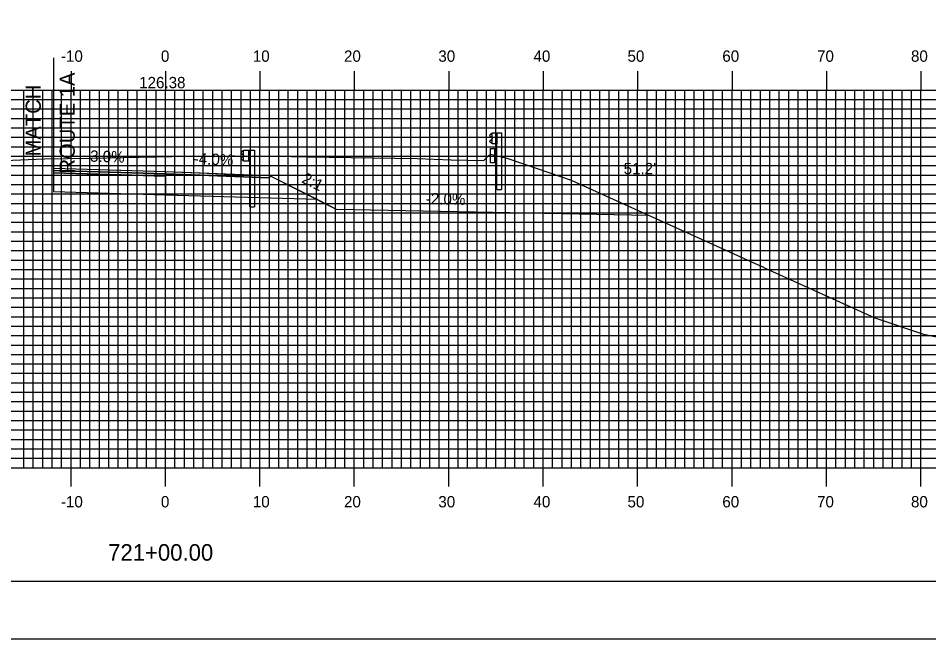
# Model space of a CAD drawing. Extents: x 858445 to 858788, y 364366 to 364586.
# Drawn here: x 858595.3 to 858691.7, y 364365.7 to 364431.4 of the extents above; entities that cross this region are included whole.
import ezdxf

# ---------------------------------------------------------------- set-up
doc = ezdxf.new("R2010")
doc.units = 0
for name, color, linetype in [('ANNOTATION', 7, 'Continuous'), ('BORDER', 7, 'Continuous'), ('D_Guardrail_Beam_Lt', 7, 'Continuous'), ('D_Roadway_Centerline', 7, 'Continuous'), ('D_Roadway_Centerline_Text', 7, 'Continuous'), ('D_Roadway_Edge_Shoulder', 7, 'Continuous'), ('D_Roadway_Edge_TW', 7, 'Continuous'), ('D_Roadway_Pavement', 7, 'Continuous'), ('D_Roadway_SlopeLines', 7, 'Continuous'), ('D_Roadway_SubGrade', 7, 'Continuous'), ('D_Text_Standard', 7, 'Continuous'), ('H_V ANNOTATION', 7, 'Continuous'), ('M_Roadway_Centerline', 7, 'Continuous'), ('MAJOR', 7, 'Continuous'), ('MINOR', 7, 'Continuous'), ('PLOT BOUNDARY', 7, 'Continuous'), ('S_Curb_Type_1', 7, 'Continuous'), ('S_Guardrail_Beam', 7, 'Continuous'), ('S_Roadway_Centerline', 7, 'Continuous')]:
    doc.layers.add(name, color=color, linetype=linetype)

msp = doc.modelspace()

# ---------------------------------------------------------------- linework, layer by layer
at = {"layer": 'BORDER'}
msp.add_lwpolyline([(858461.275, 364371.787), (858781.275, 364371.787), (858781.275, 364581.787), (858461.275, 364581.787)], close=True, dxfattribs=at)
at = {"layer": 'D_Guardrail_Beam_Lt'}
for p, q in [((858619.056, 364417.325), (858618.912, 364417.225)), ((858618.912, 364417.082), (858619.107, 364416.946)), ((858619.146, 364417.347), (858619.071, 364417.332)), ((858619.146, 364417.43), (858619.833, 364417.43)), ((858619.146, 364416.263), (858619.146, 364417.43)), ((858619.666, 364417.43), (858619.666, 364416.263)), ((858619.771, 364417.43), (858619.771, 364416.263)), ((858619.833, 364417.43), (858620.304, 364417.43)), ((858619.833, 364417.43), (858619.833, 364416.263)), ((858620.304, 364417.43), (858620.304, 364411.43)), ((858619.107, 364416.747), (858618.912, 364416.611)), ((858618.912, 364416.468), (858619.056, 364416.368)), ((858619.071, 364416.361), (858619.146, 364416.347)), ((858619.141, 364416.882), (858619.141, 364416.812)), ((858619.833, 364416.263), (858619.146, 364416.263)), ((858619.812, 364411.43), (858619.812, 364416.263)), ((858619.812, 364411.43), (858620.304, 364411.43))]:
    msp.add_line(p, q, dxfattribs=at)
for centre, major_axis, start_param, end_param in [((858618.962, 364417.154), (-0.0877, 0), 5.323254, 7.243116), ((858619.079, 364417.291), (-0.0417, 0), 4.907132, 5.323254), ((858618.962, 364416.54), (-0.0877, 0), 5.323254, 7.243116), ((858619.079, 364416.402), (-0.0417, 0), 0.959931, 1.376053), ((858619.062, 364416.882), (0.0789, 0), 0, 0.959931), ((858619.062, 364416.812), (0.0789, 0), 5.323254, 6.283185)]:
    msp.add_ellipse(centre, major_axis=major_axis, ratio=0.995501, start_param=start_param, end_param=end_param, dxfattribs=at)
at = {"layer": 'D_Roadway_Centerline'}
msp.add_lwpolyline([(858599.008, 364415.522), (858603.741, 364415.381), (858610.875, 364415.167), (858615.281, 364414.99), (858618.875, 364414.847), (858620.526, 364414.781), (858621.875, 364414.727), (858624.674, 364413.327), (858626.96, 364412.184), (858628.06, 364411.634), (858628.96, 364411.184), (858647.257, 364410.818), (858662.073, 364410.522)], dxfattribs=at)
at = {"layer": 'D_Roadway_Edge_Shoulder'}
for points in [[(858610.875, 364415.167), (858621.875, 364414.727), (858621.875, 364414.477), (858610.875, 364414.917)], [(858610.875, 364415.167), (858618.875, 364414.847), (858618.875, 364414.847), (858621.875, 364414.727), (858621.875, 364414.477), (858610.875, 364414.917)]]:
    msp.add_lwpolyline(points, close=True, dxfattribs=at)
at = {"layer": 'D_Roadway_Edge_TW'}
msp.add_lwpolyline([(858599.008, 364415.522), (858610.875, 364415.167), (858610.875, 364414.917), (858599.008, 364415.272)], dxfattribs=at)
msp.add_lwpolyline([(858599.008, 364415.522), (858610.875, 364415.167), (858610.875, 364414.917), (858599.008, 364415.272)], dxfattribs=at)
msp.add_lwpolyline([(858599.008, 364415.522), (858610.875, 364415.167), (858610.875, 364414.917), (858599.008, 364415.272)], dxfattribs=at)
at = {"layer": 'D_Roadway_Pavement'}
for points in [[(858599.008, 364415.272), (858610.875, 364414.917), (858610.875, 364414.667), (858599.008, 364415.022)], [(858599.008, 364415.272), (858610.875, 364414.917), (858610.875, 364414.667), (858599.008, 364415.022)], [(858599.008, 364415.272), (858610.875, 364414.917), (858610.875, 364414.667), (858599.008, 364415.022)], [(858610.875, 364414.917), (858610.875, 364414.667)], [(858610.875, 364414.917), (858610.875, 364414.667)], [(858610.875, 364414.917), (858610.875, 364414.667)], [(858610.875, 364414.917), (858610.875, 364414.667)]]:
    msp.add_lwpolyline(points, dxfattribs=at)
at = {"layer": 'D_Roadway_SlopeLines'}
for points in [[(858621.875, 364414.727), (858628.96, 364411.184)], [(858628.96, 364411.184), (858662.073, 364410.522)]]:
    msp.add_lwpolyline(points, dxfattribs=at)
at = {"layer": 'D_Roadway_SubGrade'}
msp.add_line((858599.008, 364427.215), (858599.008, 364413.022), dxfattribs=at)
msp.add_lwpolyline([(858599.008, 364415.022), (858610.875, 364414.667), (858610.875, 364412.667), (858599.008, 364413.022)], dxfattribs=at)
msp.add_lwpolyline([(858599.008, 364415.022), (858610.875, 364414.667), (858610.875, 364412.667), (858599.008, 364413.022)], dxfattribs=at)
msp.add_lwpolyline([(858599.008, 364415.022), (858610.875, 364414.667), (858610.875, 364412.667), (858599.008, 364413.022)], dxfattribs=at)
msp.add_lwpolyline([(858610.875, 364414.667), (858610.875, 364414.917), (858621.875, 364414.477), (858621.875, 364414.727), (858626.96, 364412.184), (858610.875, 364412.667)], close=True, dxfattribs=at)
at = {"layer": 'MAJOR'}
for p, q in [((858600.875, 364425.791), (858600.875, 364423.787)), ((858610.875, 364425.791), (858610.875, 364423.787)), ((858620.875, 364425.791), (858620.875, 364423.787)), ((858630.875, 364425.791), (858630.875, 364423.787)), ((858640.875, 364425.791), (858640.875, 364423.787)), ((858650.875, 364425.791), (858650.875, 364423.787)), ((858660.875, 364425.791), (858660.875, 364423.787)), ((858670.875, 364425.791), (858670.875, 364423.787)), ((858680.875, 364425.791), (858680.875, 364423.787)), ((858690.875, 364425.791), (858690.875, 364423.787)), ((858470.875, 364423.787), (858750.875, 364423.787)), ((858470.875, 364423.787), (858750.875, 364423.787)), ((858600.875, 364383.787), (858600.875, 364423.787)), ((858610.875, 364383.787), (858610.875, 364423.787)), ((858620.875, 364383.787), (858620.875, 364423.787)), ((858630.875, 364383.787), (858630.875, 364423.787)), ((858640.875, 364383.787), (858640.875, 364423.787)), ((858650.875, 364383.787), (858650.875, 364423.787)), ((858660.875, 364383.787), (858660.875, 364423.787)), ((858670.875, 364383.787), (858670.875, 364423.787)), ((858680.875, 364383.787), (858680.875, 364423.787)), ((858690.875, 364383.787), (858690.875, 364423.787)), ((858470.875, 364418.787), (858750.875, 364418.787)), ((858470.875, 364413.787), (858750.875, 364413.787)), ((858470.875, 364408.787), (858750.875, 364408.787)), ((858470.875, 364403.787), (858750.875, 364403.787)), ((858470.875, 364398.787), (858750.875, 364398.787)), ((858470.875, 364393.787), (858750.875, 364393.787)), ((858470.875, 364388.787), (858750.875, 364388.787)), ((858470.875, 364383.787), (858750.875, 364383.787)), ((858470.875, 364383.787), (858750.875, 364383.787)), ((858600.875, 364381.783), (858600.875, 364383.787)), ((858610.875, 364381.783), (858610.875, 364383.787)), ((858620.875, 364381.783), (858620.875, 364383.787)), ((858630.875, 364381.783), (858630.875, 364383.787)), ((858640.875, 364381.783), (858640.875, 364383.787)), ((858650.875, 364381.783), (858650.875, 364383.787)), ((858660.875, 364381.783), (858660.875, 364383.787)), ((858670.875, 364381.783), (858670.875, 364383.787)), ((858680.875, 364381.783), (858680.875, 364383.787)), ((858690.875, 364381.783), (858690.875, 364383.787))]:
    msp.add_line(p, q, dxfattribs=at)
at = {"layer": 'MINOR'}
for p, q in [((858595.875, 364383.787), (858595.875, 364423.787)), ((858596.875, 364383.787), (858596.875, 364423.787)), ((858597.875, 364383.787), (858597.875, 364423.787)), ((858598.875, 364383.787), (858598.875, 364423.787)), ((858599.875, 364383.787), (858599.875, 364423.787)), ((858601.875, 364383.787), (858601.875, 364423.787)), ((858602.875, 364383.787), (858602.875, 364423.787)), ((858603.875, 364383.787), (858603.875, 364423.787)), ((858604.875, 364383.787), (858604.875, 364423.787)), ((858605.875, 364383.787), (858605.875, 364423.787)), ((858606.875, 364383.787), (858606.875, 364423.787)), ((858607.875, 364383.787), (858607.875, 364423.787)), ((858608.875, 364383.787), (858608.875, 364423.787)), ((858609.875, 364383.787), (858609.875, 364423.787)), ((858611.875, 364383.787), (858611.875, 364423.787)), ((858612.875, 364383.787), (858612.875, 364423.787)), ((858613.875, 364383.787), (858613.875, 364423.787)), ((858614.875, 364383.787), (858614.875, 364423.787)), ((858615.875, 364383.787), (858615.875, 364423.787)), ((858616.875, 364383.787), (858616.875, 364423.787)), ((858617.875, 364383.787), (858617.875, 364423.787)), ((858618.875, 364383.787), (858618.875, 364423.787)), ((858619.875, 364383.787), (858619.875, 364423.787)), ((858621.875, 364383.787), (858621.875, 364423.787)), ((858622.875, 364383.787), (858622.875, 364423.787)), ((858623.875, 364383.787), (858623.875, 364423.787)), ((858624.875, 364383.787), (858624.875, 364423.787)), ((858625.875, 364383.787), (858625.875, 364423.787)), ((858626.875, 364383.787), (858626.875, 364423.787)), ((858627.875, 364383.787), (858627.875, 364423.787)), ((858628.875, 364383.787), (858628.875, 364423.787)), ((858629.875, 364383.787), (858629.875, 364423.787)), ((858631.875, 364383.787), (858631.875, 364423.787)), ((858632.875, 364383.787), (858632.875, 364423.787)), ((858633.875, 364383.787), (858633.875, 364423.787)), ((858634.875, 364383.787), (858634.875, 364423.787)), ((858635.875, 364383.787), (858635.875, 364423.787)), ((858636.875, 364383.787), (858636.875, 364423.787)), ((858637.875, 364383.787), (858637.875, 364423.787)), ((858638.875, 364383.787), (858638.875, 364423.787)), ((858639.875, 364383.787), (858639.875, 364423.787)), ((858641.875, 364383.787), (858641.875, 364423.787)), ((858642.875, 364383.787), (858642.875, 364423.787)), ((858643.875, 364383.787), (858643.875, 364423.787)), ((858644.875, 364383.787), (858644.875, 364423.787)), ((858645.875, 364383.787), (858645.875, 364423.787)), ((858646.875, 364383.787), (858646.875, 364423.787)), ((858647.875, 364383.787), (858647.875, 364423.787)), ((858648.875, 364383.787), (858648.875, 364423.787)), ((858649.875, 364383.787), (858649.875, 364423.787)), ((858651.875, 364383.787), (858651.875, 364423.787)), ((858652.875, 364383.787), (858652.875, 364423.787)), ((858653.875, 364383.787), (858653.875, 364423.787)), ((858654.875, 364383.787), (858654.875, 364423.787)), ((858655.875, 364383.787), (858655.875, 364423.787)), ((858656.875, 364383.787), (858656.875, 364423.787)), ((858657.875, 364383.787), (858657.875, 364423.787)), ((858658.875, 364383.787), (858658.875, 364423.787)), ((858659.875, 364383.787), (858659.875, 364423.787)), ((858661.875, 364383.787), (858661.875, 364423.787)), ((858662.875, 364383.787), (858662.875, 364423.787)), ((858663.875, 364383.787), (858663.875, 364423.787)), ((858664.875, 364383.787), (858664.875, 364423.787)), ((858665.875, 364383.787), (858665.875, 364423.787)), ((858666.875, 364383.787), (858666.875, 364423.787)), ((858667.875, 364383.787), (858667.875, 364423.787)), ((858668.875, 364383.787), (858668.875, 364423.787)), ((858669.875, 364383.787), (858669.875, 364423.787)), ((858671.875, 364383.787), (858671.875, 364423.787)), ((858672.875, 364383.787), (858672.875, 364423.787)), ((858673.875, 364383.787), (858673.875, 364423.787)), ((858674.875, 364383.787), (858674.875, 364423.787)), ((858675.875, 364383.787), (858675.875, 364423.787)), ((858676.875, 364383.787), (858676.875, 364423.787)), ((858677.875, 364383.787), (858677.875, 364423.787)), ((858678.875, 364383.787), (858678.875, 364423.787)), ((858679.875, 364383.787), (858679.875, 364423.787)), ((858681.875, 364383.787), (858681.875, 364423.787)), ((858682.875, 364383.787), (858682.875, 364423.787)), ((858683.875, 364383.787), (858683.875, 364423.787)), ((858684.875, 364383.787), (858684.875, 364423.787)), ((858685.875, 364383.787), (858685.875, 364423.787)), ((858686.875, 364383.787), (858686.875, 364423.787)), ((858687.875, 364383.787), (858687.875, 364423.787)), ((858688.875, 364383.787), (858688.875, 364423.787)), ((858689.875, 364383.787), (858689.875, 364423.787)), ((858470.875, 364422.787), (858750.875, 364422.787)), ((858470.875, 364421.787), (858750.875, 364421.787)), ((858470.875, 364420.787), (858750.875, 364420.787)), ((858470.875, 364419.787), (858750.875, 364419.787)), ((858470.875, 364417.787), (858750.875, 364417.787)), ((858470.875, 364416.787), (858750.875, 364416.787)), ((858470.875, 364415.787), (858750.875, 364415.787)), ((858470.875, 364414.787), (858750.875, 364414.787)), ((858470.875, 364412.787), (858750.875, 364412.787)), ((858470.875, 364411.787), (858750.875, 364411.787)), ((858470.875, 364410.787), (858750.875, 364410.787)), ((858470.875, 364409.787), (858750.875, 364409.787)), ((858470.875, 364407.787), (858750.875, 364407.787)), ((858470.875, 364406.787), (858750.875, 364406.787)), ((858470.875, 364405.787), (858750.875, 364405.787)), ((858470.875, 364404.787), (858750.875, 364404.787)), ((858470.875, 364402.787), (858750.875, 364402.787)), ((858470.875, 364401.787), (858750.875, 364401.787)), ((858470.875, 364400.787), (858750.875, 364400.787)), ((858470.875, 364399.787), (858750.875, 364399.787)), ((858470.875, 364397.787), (858750.875, 364397.787)), ((858470.875, 364396.787), (858750.875, 364396.787)), ((858470.875, 364395.787), (858750.875, 364395.787)), ((858470.875, 364394.787), (858750.875, 364394.787)), ((858470.875, 364392.787), (858750.875, 364392.787)), ((858470.875, 364391.787), (858750.875, 364391.787)), ((858470.875, 364390.787), (858750.875, 364390.787)), ((858470.875, 364389.787), (858750.875, 364389.787)), ((858470.875, 364387.787), (858750.875, 364387.787)), ((858470.875, 364386.787), (858750.875, 364386.787)), ((858470.875, 364385.787), (858750.875, 364385.787)), ((858470.875, 364384.787), (858750.875, 364384.787))]:
    msp.add_line(p, q, dxfattribs=at)
at = {"layer": 'PLOT BOUNDARY'}
msp.add_lwpolyline([(858445.088, 364365.669), (858785.088, 364365.669), (858785.088, 364585.669), (858445.088, 364585.669)], close=True, dxfattribs=at)
at = {"layer": 'S_Curb_Type_1'}
msp.add_lwpolyline([(858645.295, 364417.594), (858645.711, 364417.594), (858645.711, 364416.094), (858645.295, 364416.094)], close=True, dxfattribs=at)
msp.add_lwpolyline([(858645.295, 364417.594), (858645.711, 364417.594), (858645.711, 364416.094), (858645.295, 364416.094)], close=True, dxfattribs=at)
at = {"layer": 'S_Guardrail_Beam'}
for p, q in [((858645.387, 364419.162), (858645.244, 364419.062)), ((858645.387, 364419.162), (858645.244, 364419.062)), ((858645.244, 364418.919), (858645.439, 364418.783)), ((858645.244, 364418.919), (858645.439, 364418.783)), ((858645.486, 364419.183), (858645.404, 364419.169)), ((858645.486, 364419.183), (858645.404, 364419.169)), ((858645.486, 364419.256), (858645.976, 364419.256)), ((858645.486, 364418.09), (858645.486, 364419.256)), ((858645.486, 364419.256), (858645.976, 364419.256)), ((858645.486, 364418.09), (858645.486, 364419.256)), ((858645.976, 364419.256), (858646.467, 364419.256)), ((858645.976, 364419.256), (858645.976, 364418.09)), ((858645.976, 364419.256), (858646.467, 364419.256)), ((858645.976, 364419.256), (858645.976, 364418.09)), ((858646.467, 364419.256), (858646.467, 364413.256)), ((858646.467, 364419.256), (858646.467, 364413.256)), ((858645.439, 364418.563), (858645.244, 364418.427)), ((858645.439, 364418.563), (858645.244, 364418.427)), ((858645.244, 364418.284), (858645.387, 364418.184)), ((858645.244, 364418.284), (858645.387, 364418.184)), ((858645.404, 364418.177), (858645.486, 364418.162)), ((858645.404, 364418.177), (858645.486, 364418.162)), ((858645.473, 364418.718), (858645.473, 364418.627)), ((858645.473, 364418.718), (858645.473, 364418.627)), ((858645.976, 364418.09), (858645.486, 364418.09)), ((858645.976, 364418.09), (858645.486, 364418.09)), ((858645.976, 364413.256), (858645.976, 364418.09)), ((858645.976, 364413.256), (858645.976, 364418.09)), ((858645.976, 364413.256), (858646.467, 364413.256)), ((858645.976, 364413.256), (858646.467, 364413.256))]:
    msp.add_line(p, q, dxfattribs=at)
for centre, major_axis, start_param, end_param in [((858645.294, 364418.99), (-0.0877, 0), 5.323254, 7.243116), ((858645.294, 364418.99), (-0.0877, 0), 5.323254, 7.243116), ((858645.411, 364419.128), (-0.0417, 0), 4.886922, 5.323254), ((858645.411, 364419.128), (-0.0417, 0), 4.886922, 5.323254), ((858645.294, 364418.355), (-0.0877, 0), 5.323254, 7.243116), ((858645.294, 364418.355), (-0.0877, 0), 5.323254, 7.243116), ((858645.411, 364418.218), (-0.0417, 0), 0.959931, 1.396263), ((858645.411, 364418.218), (-0.0417, 0), 0.959931, 1.396263), ((858645.394, 364418.718), (0.0789, 0), 0, 0.959931), ((858645.394, 364418.718), (0.0789, 0), 0, 0.959931), ((858645.394, 364418.627), (0.0789, 0), 5.323254, 6.283185), ((858645.394, 364418.627), (0.0789, 0), 5.323254, 6.283185)]:
    msp.add_ellipse(centre, major_axis=major_axis, ratio=0.995501, start_param=start_param, end_param=end_param, dxfattribs=at)
at = {"layer": 'S_Roadway_Centerline'}
msp.add_lwpolyline([(858590.488, 364416.187), (858597.181, 364416.464), (858598.053, 364416.495), (858602.925, 364416.571), (858611.563, 364416.74), (858617.848, 364416.824), (858618.173, 364416.83), (858623.297, 364416.774), (858624.205, 364416.759), (858625.876, 364416.729), (858637.517, 364416.525), (858641.13, 364416.409), (858644.593, 364416.342), (858644.952, 364416.712), (858645.295, 364417.01), (858646.013, 364416.835), (858647.021, 364416.592), (858650.328, 364415.463), (858653.847, 364414.247), (858674.022, 364405.111), (858674.075, 364405.09), (858674.394, 364404.942), (858685.995, 364399.657), (858691.159, 364397.944), (858707.284, 364394.6)], dxfattribs=at)

# ---------------------------------------------------------------- texts
at = {"layer": 'ANNOTATION'}
for s, height, rotation, p in [('ROUTE 1A', 1.6, 90, (858601.269, 364414.95)), ('MATCH', 1.6, 90, (858597.669, 364416.756)), ('3.0%', 1.2, 358.28355, (858602.874, 364416.207)), ('-4.0%', 1.2, 357.70939, (858613.848, 364415.947)), ('2:1', 1.2, 333.43495, (858625.213, 364414.036)), ('-2.0%', 1.2, 358.85424, (858638.433, 364411.7))]:
    msp.add_text(s, height=height, rotation=rotation, dxfattribs=at).set_placement(p)
at = {"layer": 'D_Roadway_Centerline_Text'}
msp.add_text('126.38', height=1.2, dxfattribs=at).set_placement((858608.087, 364423.984))
at = {"layer": 'D_Text_Standard'}
msp.add_text("51.2'", height=1.2, dxfattribs=at).set_placement((858659.395, 364414.873))
at = {"layer": 'H_V ANNOTATION'}
for s, height, p in [('-10', 1.2, (858599.804, 364426.787)), ('0', 1.2, (858610.393, 364426.787)), ('10', 1.2, (858620.125, 364426.787)), ('20', 1.2, (858629.783, 364426.787)), ('30', 1.2, (858639.772, 364426.787)), ('40', 1.2, (858649.847, 364426.787)), ('50', 1.2, (858659.804, 364426.787)), ('60', 1.2, (858669.847, 364426.787)), ('70', 1.2, (858679.879, 364426.787)), ('80', 1.2, (858689.826, 364426.787)), ('-10', 1.2, (858599.804, 364379.587)), ('0', 1.2, (858610.393, 364379.587)), ('10', 1.2, (858620.125, 364379.587)), ('20', 1.2, (858629.783, 364379.587)), ('30', 1.2, (858639.772, 364379.587)), ('40', 1.2, (858649.847, 364379.587)), ('50', 1.2, (858659.804, 364379.587)), ('60', 1.2, (858669.847, 364379.587)), ('70', 1.2, (858679.879, 364379.587)), ('80', 1.2, (858689.826, 364379.587)), ('721+00.00', 1.75, (858604.804, 364373.943))]:
    msp.add_text(s, height=height, dxfattribs=at).set_placement(p)
at = {"layer": 'M_Roadway_Centerline'}
for s, p in [('C', (858618.167, 364416.83)), ('L', (858618.173, 364416.823))]:
    msp.add_text(s, height=0.0146, dxfattribs=at).set_placement(p)

doc.saveas('drawing.dxf')
